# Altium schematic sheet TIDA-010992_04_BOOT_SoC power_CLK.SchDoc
size 431 x 279 mm; Date: Not shown in title block; ApprovedBy: Not shown in title block; CheckedBy: Not shown in title block; Author: Not shown in title block; CompanyName: Not shown in title block; Engineer: Not shown in title block; Organization: Not shown in title block; Address1: Not shown in title block; Address2: Not shown in title block; Address3: Not shown in title block; Address4: Not shown in title block; DocumentNumber: 4; Revision: Use project parameter SCH_Rev; SheetNumber: 4; SheetTotal: 13; PageSetup: Record=PageOptions¦CenterHorizontal=True¦CenterVertical=True¦PrintScale=1.00¦XCorrection=1.00¦YCorrection=1.00¦PrintKind=0¦BorderSize=5000000¦LeftOffset=0¦BottomOffset=0¦Orientation=2¦PaperLength=1000¦PaperWidth=1000¦Scale=100¦PaperSource=15¦PrintQuality=600¦MediaType=1¦DitherType=10¦PaperKind=Letter¦PrintScaleMode=1
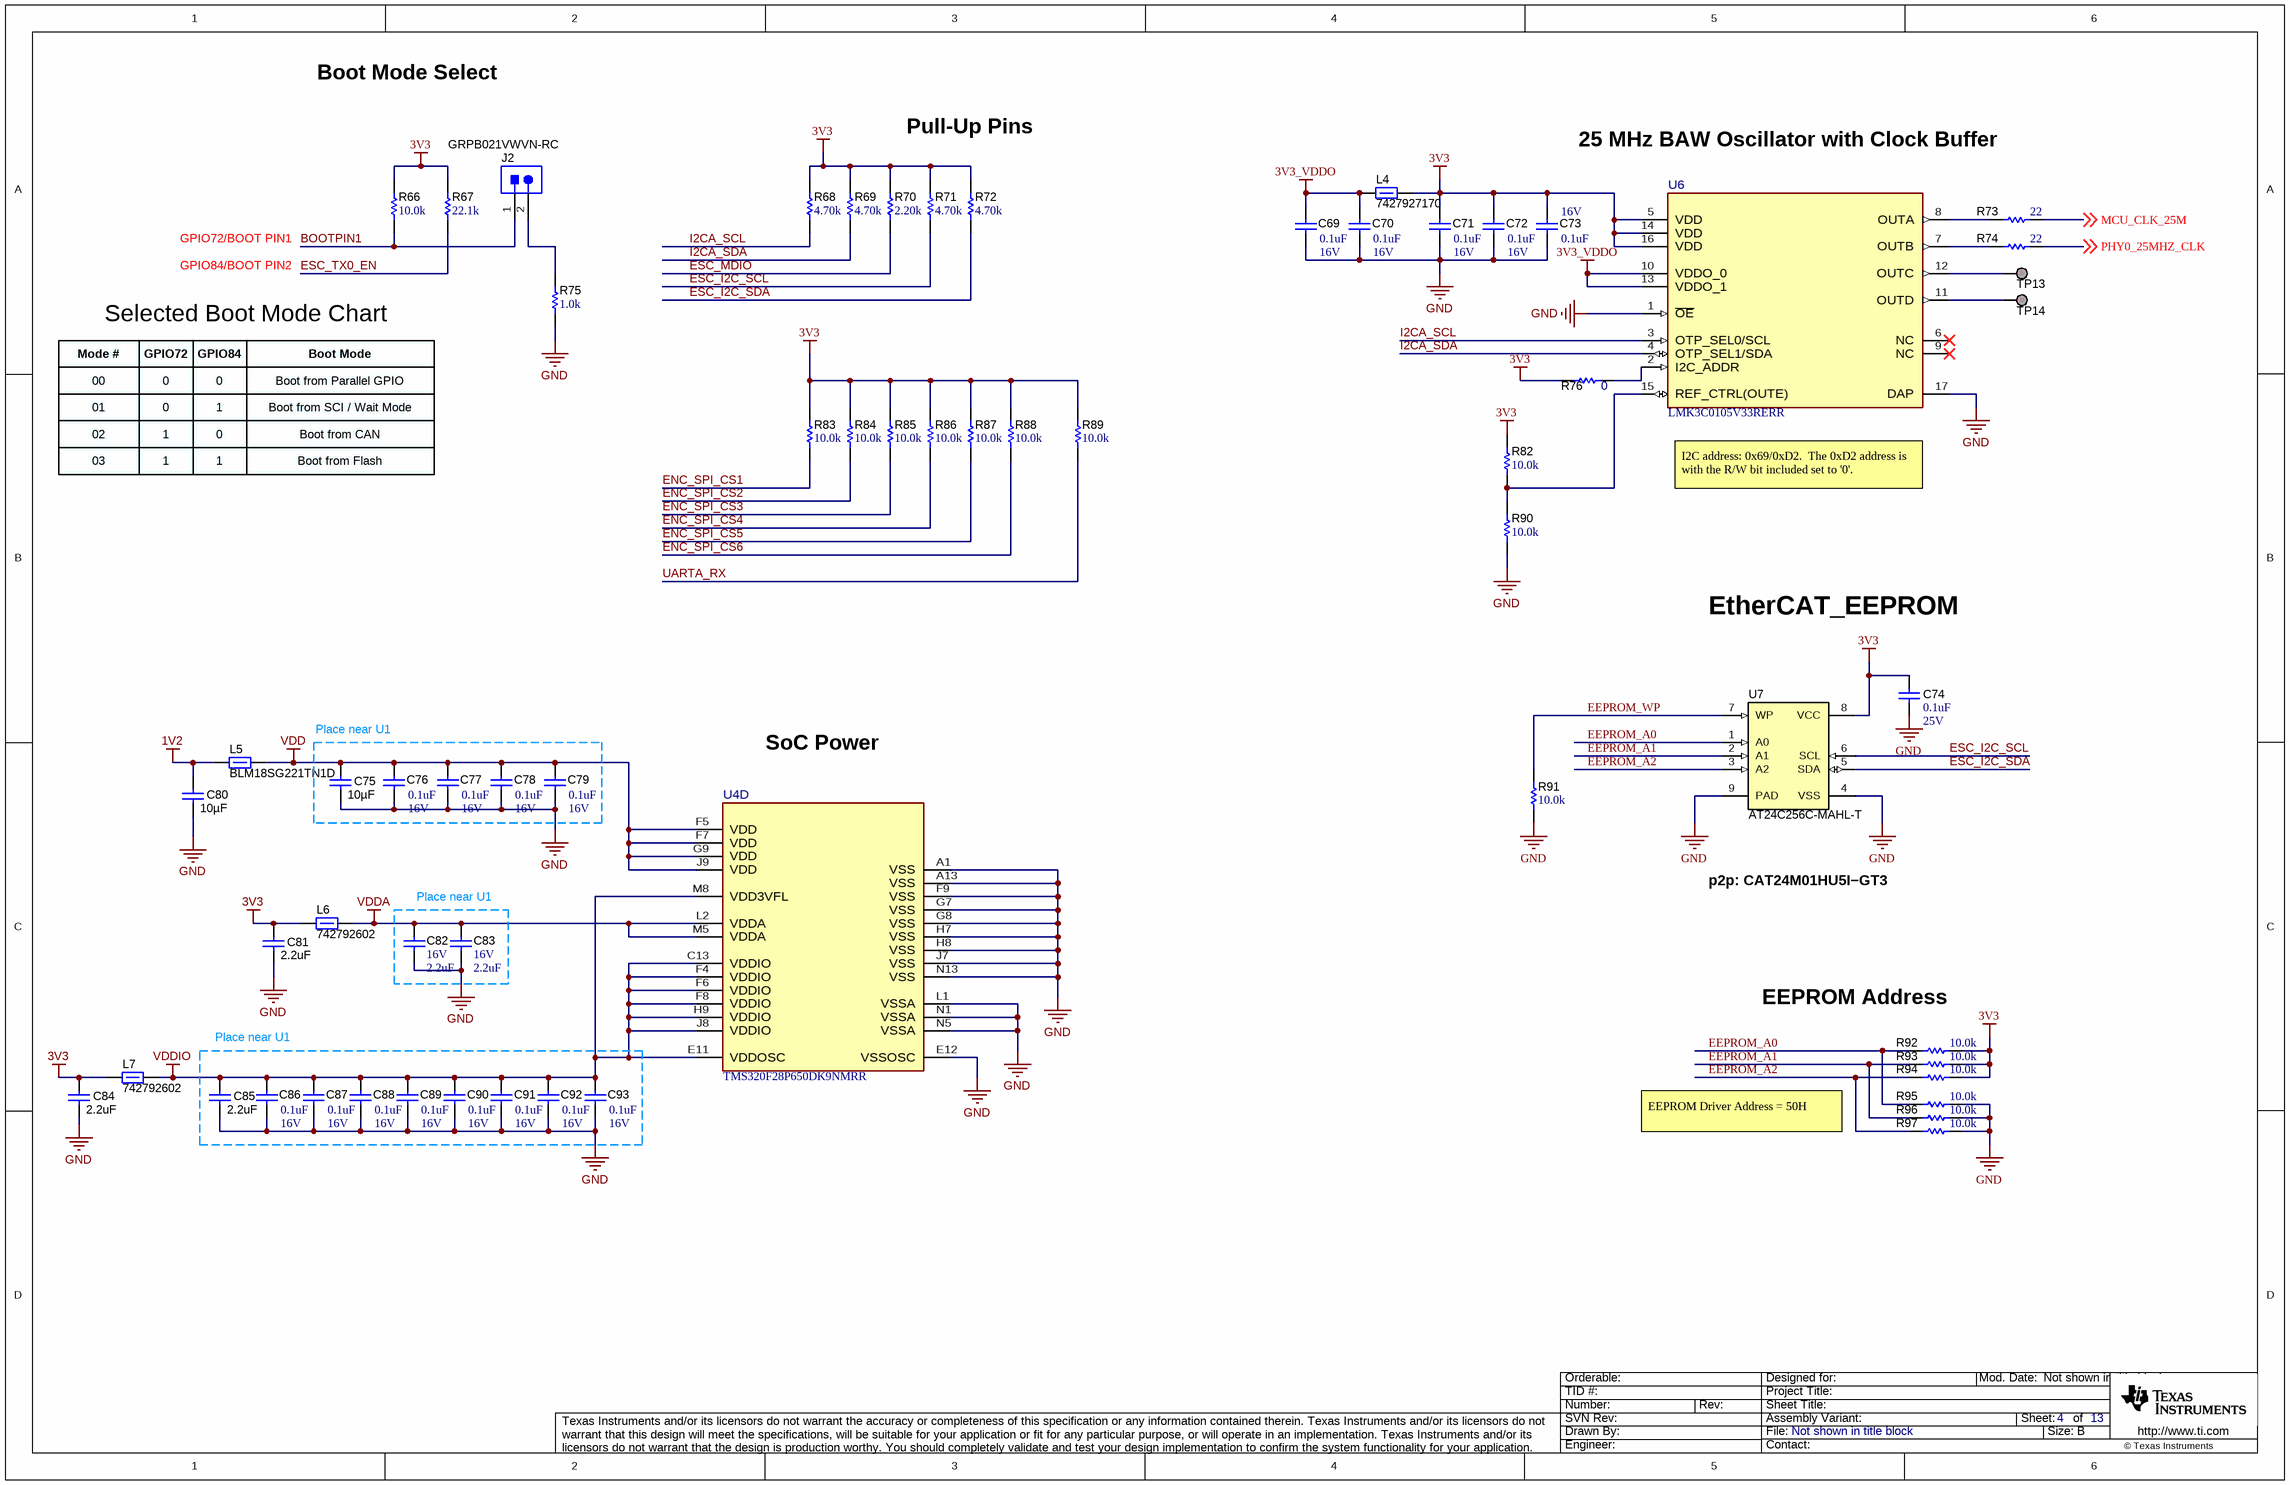
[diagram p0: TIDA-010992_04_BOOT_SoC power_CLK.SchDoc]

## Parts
C69  VDC_V: 16V  ValueDisplayed: 0.1uF  [0201]  (hidden comment: GRM033Z71C104KE14D)
C70  VDC_V: 16V  ValueDisplayed: 0.1uF  [0201]  (hidden comment: GRM033Z71C104KE14D)
C71  VDC_V: 16V  ValueDisplayed: 0.1uF  [0201]  (hidden comment: GRM033Z71C104KE14D)
C72  VDC_V: 16V  ValueDisplayed: 0.1uF  [0201]  (hidden comment: GRM033Z71C104KE14D)
C73  VDC_V: 16V  ValueDisplayed: 0.1uF  [0201]  (hidden comment: GRM033Z71C104KE14D)
C74  Value2: 25V  ValueDisplayed: 0.1uF  [0402]  (hidden comment: GRM155R71E104KE14D)
C75  ValueDisplayed: 10µF  [0603]  (hidden comment: GRM188R61C106KAALD)
C76  VDC_V: 16V  ValueDisplayed: 0.1uF  [0201]  (hidden comment: GRM033Z71C104KE14D)
C77  VDC_V: 16V  ValueDisplayed: 0.1uF  [0201]  (hidden comment: GRM033Z71C104KE14D)
C78  VDC_V: 16V  ValueDisplayed: 0.1uF  [0201]  (hidden comment: GRM033Z71C104KE14D)
C79  VDC_V: 16V  ValueDisplayed: 0.1uF  [0201]  (hidden comment: GRM033Z71C104KE14D)
C80  ValueDisplayed: 10µF  [0603]  (hidden comment: GRM188R61C106KAALD)
C81  ValueDisplayed: 2.2uF  [0603]  (hidden comment: 885012106018)
C82  VDC_V: 16V  ValueDisplayed: 2.2uF  [0402]  (hidden comment: GRM155R61C225KE11D)
C83  VDC_V: 16V  ValueDisplayed: 2.2uF  [0402]  (hidden comment: GRM155R61C225KE11D)
C84  ValueDisplayed: 2.2uF  [0603]  (hidden comment: 885012106018)
C85  ValueDisplayed: 2.2uF  [0603]  (hidden comment: 885012106018)
C86  VDC_V: 16V  ValueDisplayed: 0.1uF  [0201]  (hidden comment: GRM033Z71C104KE14D)
C87  VDC_V: 16V  ValueDisplayed: 0.1uF  [0201]  (hidden comment: GRM033Z71C104KE14D)
C88  VDC_V: 16V  ValueDisplayed: 0.1uF  [0201]  (hidden comment: GRM033Z71C104KE14D)
C89  VDC_V: 16V  ValueDisplayed: 0.1uF  [0201]  (hidden comment: GRM033Z71C104KE14D)
C90  VDC_V: 16V  ValueDisplayed: 0.1uF  [0201]  (hidden comment: GRM033Z71C104KE14D)
C91  VDC_V: 16V  ValueDisplayed: 0.1uF  [0201]  (hidden comment: GRM033Z71C104KE14D)
C92  VDC_V: 16V  ValueDisplayed: 0.1uF  [0201]  (hidden comment: GRM033Z71C104KE14D)
C93  VDC_V: 16V  ValueDisplayed: 0.1uF  [0201]  (hidden comment: GRM033Z71C104KE14D)
J2  GRPB021VWVN-RC  [Sullins_GRPB021VWVN-RC]
L4  7427927170  [0402]
L5  BLM18SG221TN1D  [0603]
L6  742792602  [0603]
L7  742792602  [0603]
R66  ValueDisplayed: 10.0k  [0402]  (hidden comment: ERJ-2RKF1002X)
R67  ValueDisplayed: 22.1k  [0402]  (hidden comment: CRCW040222K1FKED)
R68  ValueDisplayed: 4.70k  [0201]  (hidden comment: RC0201FR-7D4K7L)
R69  ValueDisplayed: 4.70k  [0201]  (hidden comment: RC0201FR-7D4K7L)
R70  ValueDisplayed: 2.20k  [0201]  (hidden comment: RC0201FR-072K2L)
R71  ValueDisplayed: 4.70k  [0201]  (hidden comment: RC0201FR-7D4K7L)
R72  ValueDisplayed: 4.70k  [0201]  (hidden comment: RC0201FR-7D4K7L)
R73  ValueDisplayed: 22  [0402L]  (hidden comment: CRCW040222R0JNED)
R74  ValueDisplayed: 22  [0402L]  (hidden comment: CRCW040222R0JNED)
R75  ValueDisplayed: 1.0k  [0402]  (hidden comment: ERJ-2GEJ102X)
R76  ValueDisplayed: 0  [0402]  (hidden comment: CRCW04020000Z0EDHP)
R82  ValueDisplayed: 10.0k  [0201]  (hidden comment: RC0201FS-7D10KL)
R83  ValueDisplayed: 10.0k  [0201]  (hidden comment: RC0201FS-7D10KL)
R84  ValueDisplayed: 10.0k  [0201]  (hidden comment: RC0201FS-7D10KL)
R85  ValueDisplayed: 10.0k  [0201]  (hidden comment: RC0201FS-7D10KL)
R86  ValueDisplayed: 10.0k  [0201]  (hidden comment: RC0201FS-7D10KL)
R87  ValueDisplayed: 10.0k  [0201]  (hidden comment: RC0201FS-7D10KL)
R88  ValueDisplayed: 10.0k  [0201]  (hidden comment: RC0201FS-7D10KL)
R89  ValueDisplayed: 10.0k  [0201]  (hidden comment: RC0201FS-7D10KL)
R90  ValueDisplayed: 10.0k  [0201]  (hidden comment: RC0201FS-7D10KL)
R91  ValueDisplayed: 10.0k  [0402]  (hidden comment: ERJ-2RKF1002X)
R92  ValueDisplayed: 10.0k  [0402]  (hidden comment: ERJ-2RKF1002X)
R93  ValueDisplayed: 10.0k  [0402]  (hidden comment: ERJ-2RKF1002X)
R94  ValueDisplayed: 10.0k  [0402]  (hidden comment: ERJ-2RKF1002X)
R95  ValueDisplayed: 10.0k  [0402]  (hidden comment: ERJ-2RKF1002X)
R96  ValueDisplayed: 10.0k  [0402]  (hidden comment: ERJ-2RKF1002X)
R97  ValueDisplayed: 10.0k  [0402]  (hidden comment: ERJ-2RKF1002X)
TP13  TP_SM_1MM  [TP_SM_1MM]  (value not drawn)  (no BOM)
TP14  TP_SM_1MM  [TP_SM_1MM]  (value not drawn)  (no BOM)
U4  TMS320F28P650DK9NMRR  [NMR0169A-MFG]  (part D of 4)
U6  LMK3C0105V33RERR  [RER0016A-MFG]
U7  AT24C256C-MAHL-T  [8MA2]

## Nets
1V2: C80.1 L5.1
3V3: C71.1 C72.1 C73.1 C74.2 C81.1 C84.1 L4.1 L6.1 L7.1 R66.1 R67.2 R68.2 R69.2 R70.2 R71.2 R72.2 R76.1 R82.2 R83.2 R84.2 R85.2 R86.2 R87.2 R88.2 R89.2 R92.1 R93.1 R94.1 U6.5(VDD) U6.14(VDD) U6.16(VDD) U7.8(VCC)
3V3_VDDO: C69.1 C70.1 L4.2 U6.10(VDDO_0) U6.13(VDDO_1)
GND: C69.2 C70.2 C71.2 C72.2 C73.2 C74.1 C75.2 C76.2 C77.2 C78.2 C79.2 C80.2 C81.2 C82.2 C83.2 C84.2 C85.2 C86.2 C87.2 C88.2 C89.2 C90.2 C91.2 C92.2 C93.2 R75.1 R90.1 R91.2 R95.1 R96.1 R97.1 U4.A1(VSS) U4.A13(VSS) U4.E12(VSSOSC) U4.F9(VSS) U4.G7(VSS) U4.G8(VSS) U4.H7(VSS) U4.H8(VSS) U4.J7(VSS) U4.L1(VSSA) U4.N1(VSSA) U4.N5(VSSA) U4.N13(VSS) U6.1(~{OE}) U6.17(DAP) U7.4(VSS) U7.9(PAD)
VDD: C75.1 C76.1 C77.1 C78.1 C79.1 L5.2 U4.F5(VDD) U4.F7(VDD) U4.G9(VDD) U4.J9(VDD)
VDDA: C82.1 C83.1 L6.2 U4.L2(VDDA) U4.M5(VDDA)
VDDIO: C85.1 C86.1 C87.1 C88.1 C89.1 C90.1 C91.1 C92.1 C93.1 L7.2 U4.C13(VDDIO) U4.E11(VDDOSC) U4.F4(VDDIO) U4.F6(VDDIO) U4.F8(VDDIO) U4.H9(VDDIO) U4.J8(VDDIO) U4.M8(VDD3VFL)
BOOTPIN1: J2.1 R66.2
EEPROM_A0: R92.2 R95.2 U7.1(A0)
EEPROM_A1: R93.2 R96.2 U7.2(A1)
EEPROM_A2: R94.2 R97.2 U7.3(A2)
EEPROM_WP: R91.1 U7.7(WP)
ENC_SPI_CS1: R83.1
ENC_SPI_CS2: R84.1
ENC_SPI_CS3: R85.1
ENC_SPI_CS4: R86.1
ENC_SPI_CS5: R87.1
ENC_SPI_CS6: R88.1
ESC_I2C_SCL: R71.1 U7.6(SCL)
ESC_I2C_SDA: R72.1 U7.5(SDA)
ESC_MDIO: R70.1
ESC_TX0_EN: R67.1
I2CA_SCL: R68.1 U6.3(OTP_SEL0/SCL)
I2CA_SDA: R69.1 U6.4(OTP_SEL1/SDA)
MCU_CLK_25M: R73.2 ; off-sheet MCU_CLK_25M
PHY0_25MHZ_CLK: R74.2 ; off-sheet PHY0_25MHZ_CLK
UARTA_RX: R89.1
NetJ2_2: J2.2 R75.2
NetR73_1: R73.1 U6.8(OUTA)
NetR74_1: R74.1 U6.7(OUTB)
NetR76_2: R76.2 U6.2(I2C_ADDR)
NetR82_1: R82.1 R90.2 U6.15(REF_CTRL(OUTE))
NetTP13_1: TP13.1 U6.12(OUTC)
NetTP14_1: TP14.1 U6.11(OUTD)

Not connected (* = marked no-connect by the designer): U6 6(NC)* 9(NC)*

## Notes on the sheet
- Boot Mode Select
- Pull-Up Pins
- 25 MHz BAW Oscillator with Clock Buffer
- GPIO72/BOOT PIN1
- GPIO84/BOOT PIN2
- Mode #
- GPIO72
- GPIO84
- Selected Boot Mode Chart
- Boot Mode
- 00
- 01
- 02
- 0
- 1
- Boot from Parallel GPIO
- Boot from SCI / Wait Mode
- Boot from CAN
- 03
- Boot from Flash
- (near U6) I2C address: 0x69/0xD2.  The 0xD2 address is with the R/W bit included set to '0'.
- EtherCAT_EEPROM
- Place near U1
- SoC Power
- p2p: CAT24M01HU5I−GT3
- EEPROM Address
- EEPROM Driver Address = 50H

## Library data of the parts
C69-C73 C76-C79 C86-C93 = CMP-0064970-1: CAP, CERM, 0.1 uF, 16 V,+/- 10%, X7R, 0201; Manufacturer: MuRata; TaMin_C: -55°C; Polarized: N; SizeAreaWB_mm2: 2.08; Value1: Unknown; U/M: EA; Value: 0.1uF; TaMax_C: 125°C; SizeZ_mm: 0.26; SizeX_mm: 0.6; SizeY_mm: 0.3; SizeArea_mm2: 0.18; Cap_F: 100nF; AEC Category: Q200
C74 = CMP-0006659-2: CAP, CERM, 0.1 uF, 25 V, +/- 10%, X7R, 0402; Manufacturer: MuRata; TaMin_C: -55°C; Polarized: N; SizeAreaWB_mm2: 3; U/M: EA; Value: 0.1uF; TaMax_C: 125°C; SizeZ_mm: 0.6; SizeX_mm: 1; SizeY_mm: 0.5; Cap_F: 100nF; AEC Category: Q200; Value1: Unknown
C75 C80 = CMP-0086225-1: CAP, CERM, 10 µF, 16 V,+/- 10%, X5R, 0603; Manufacturer: MuRata; SizeZ_mm: 1; SizeX_mm: 1.6; SizeArea_mm2: 1.28; VDC_V: 16V; U/M: EA; AEC Category: Q200; SizeY_mm: 0.8; Polarized: N; TaMax_C: 85°C; Value: 10uF; SizeAreaWB_mm2: 4.68; TaMin_C: -55°C
C81 C84 C85 = CMP-0006825-5: CAP, CERM, 2.2 uF, 16 V, +/- 20%, X5R, 0603; Manufacturer: Wurth Elektronik; TaMin_C: -55°C; Polarized: N; SizeAreaWB_mm2: 4.68; Value1: Unknown; U/M: EA; Value: 2.2uF; TaMax_C: 85°C; SizeZ_mm: 1; SizeX_mm: 1.6; SizeY_mm: 0.8; Value2: 16V; SizeArea_mm2: 1.28; Cap_F: 2.2µF; AEC Category: Q200
C82 C83 = CMP-0006594-2: CAP, CERM, 2.2 uF, 16 V, +/- 10%, X5R, 0402; Manufacturer: MuRata; TaMin_C: -55°C; Polarized: N; SizeAreaWB_mm2: 3; Value1: Unknown; U/M: EA; Value: 2.2uF; TaMax_C: 85°C; SizeZ_mm: 0.6; SizeX_mm: 1; SizeY_mm: 0.5; Cap_F: 2.2µF; AEC Category: Q200
J2 = CMP-0054555-1: Header, 50mil, 2x1, Gold, TH; Manufacturer: Sullins Connector Solutions; CNHeader: TRUE; Green_Lifecycle: Not Set; Green_REACh: Incomplete; CT: FALSE
L4 = CMP-0003226-1: Ferrite Bead, 75 ohm @ 100 MHz, 0.3 A, 0402; Manufacturer: Wurth Elektronik; Ztyp@1GHz_Ohm: 541.253; ZTyp@100MHz_Ohm: 75; SizeAreaWB_mm2: 3; DCR_ohm: 0.31; Value1: 0.31 ohm; Value: 75 ohm; Imax_A: 300mA; SizeZ_mm: 0.6; SizeX_mm: 1; SizeY_mm: 0.5; Value2: 0.3A
L5 = CMP-0003353-2: Ferrite Bead, 220 ohm @ 100 MHz, 2.5 A, 0603; Manufacturer: MuRata; ZTyp@100MHz_Ohm: 220; SizeAreaWB_mm2: 4.68; DCR_ohm: 40m; Value1: 0.04 ohm; Value: 220 ohm; Imax_A: 2.5A; SizeZ_mm: 1; SizeX_mm: 1.6; SizeY_mm: 0.8; SizeArea_mm2: 1.28
L6 L7 = CMP-0003173-2: Ferrite Bead, 60 ohm @ 100 MHz, 3 A, 0603; Manufacturer: Wurth Elektronik; Ztyp@1GHz_Ohm: 110.436; ZTyp@100MHz_Ohm: 60; SizeAreaWB_mm2: 4.68; DCR_ohm: 40m; Value1: 0.04 ohm; Value: 60 ohm; Imax_A: 3A; SizeZ_mm: 1; SizeX_mm: 1.6; SizeY_mm: 0.8; SizeArea_mm2: 1.28
R66 R91-R97 = CMP-0026658-1: RES, 10.0 k, 1%, 0.1 W, 0402; Manufacturer: Panasonic; Power_W: 100mW; TempCo: 100 ppm/C; Value_Code: 10k0; U/M: EA; Value: 10.0k; EIA_Code: E96; Res_ohm: 10k; SizeX_mm: 1; SizeY_mm: 0.5; SizeZ_mm: 0.6; Value2: 0.1W; VDC_V: 50V; AEC Category: Q200
R67 = CMP-0026178-2: RES, 22.1 k, 1%, 0.063 W, AEC-Q200 Grade 0, 0402; Manufacturer: Vishay-Dale; Power_W: 63mW; TempCo: 100 ppm/C; Value_Code: 22k1; Value: 22.1k; EIA_Code: E96; SizeX_mm: 1; SizeY_mm: 0.5; SizeZ_mm: 0.6; Value2: 0.063W; AEC Qualified: Y; VDC_V: 50V; AEC Category: Q200; AEC Grade: 0
R68 R69 R71 R72 = CMP-0028031-1: RES, 4.70 k, 1%, 0.05 W, 0201; Manufacturer: Yageo America; Power_W: 50mW; TempCo: 200 ppm/C; Value_Code: 4k70; U/M: EA; Value: 4.70k; Res_ohm: 4.7k; SizeX_mm: 0.6; SizeY_mm: 0.3; SizeZ_mm: 0.26; Value2: 0.05W; SizeArea_mm2: 0.18; AEC Qualified: N; VDC_V: 25V; AEC Category: Q200
R70 = CMP-0027558-1: RES, 2.20 k, 1%, 0.05 W, 0201; Manufacturer: Yageo America; Power_W: 50mW; TempCo: 200 ppm/C; Value_Code: 2k20; U/M: EA; Value: 2.20k; Res_ohm: 2.2k; SizeX_mm: 0.6; SizeY_mm: 0.3; SizeZ_mm: 0.26; Value2: 0.05W; SizeArea_mm2: 0.18; AEC Qualified: N; VDC_V: 25V; AEC Category: Q200
R73 R74 = CMP-0026880-3: RES, 22, 5%, 0.063 W, AEC-Q200 Grade 0, 0402; Manufacturer: Vishay-Dale; Power_W: 63mW; TempCo: 200 ppm/C; Value_Code: 22R0; Value: 22; EIA_Code: E24; SizeX_mm: 1; SizeY_mm: 0.5; SizeZ_mm: 0.6; Value2: 0.063W; AEC Qualified: Y; VDC_V: 50V; AEC Category: Q200; AEC Grade: 0
R75 = CMP-0078193-1: RES, 1.0 k, 5%, 0.1 W, AEC-Q200 Grade 0, 0402; Manufacturer: Panasonic; Value_Code: 1k00; SizeArea_mm2: 0.5; AEC Qualified: Y; AEC Category: Q200; Res_ohm: 1k; Value: 1.0k; SizeZ_mm: 0.6; Green_REACh: Passed; EIA_Code: E24; TempCo: 200 ppm/C; AEC Grade: 0; Power_W: 100mW; VDC_V: 50V; Value2: 0.1W; Green_Lifecycle: Active; U/M: EA; SizeX_mm: 1
R76 = CMP-0081856-1: RES, 0, 0%, 0.2 W, AEC-Q200 Grade 0, 0402; Manufacturer: Vishay-Dale; SizeAreaWB_mm2: 3; SizeArea_mm2: 0.5; AEC Qualified: Y; AEC Category: Q200; Value: 0; SizeZ_mm: 0.6; Power_W: 200mW; VDC_V: 50V; Value2: 0.2W; SizeX_mm: 1
R82-R90 = CMP-0028071-1: RES, 10.0 k, 1%, 0.05 W, 0201; Manufacturer: Yageo America; Power_W: 50mW; TempCo: 200 ppm/C; Value_Code: 10k0; U/M: EA; Value: 10.0k; EIA_Code: E96; Res_ohm: 10k; SizeX_mm: 0.6; SizeY_mm: 0.3; SizeZ_mm: 0.26; Value2: 0.05W; SizeArea_mm2: 0.18; AEC Qualified: N; VDC_V: 25V; AEC Category: Q200
TP13 TP14 = CMP-0003825-1: 1mm Test Point, SMT; Manufacturer: Any
U4 = CMP-0098413-1: Real-Time Microcontroller, NFBGA169; Manufacturer: Texas Instruments; SizeZ_mm: 1mm; AEC Qualified: No; Core Architecture: C28x; Data Bus Width: 32bits; Frequency_Fixed: 200MHz; Interface: I2C,SPI,UART,CAN,USB,LIN,SCI,Ethernet; Max Supply Voltage: 3.63V; Memory Size: 1.28MBytes; Memory Type: FLASH; Min Supply Voltage: 1.14V; Number Of A/D Converters: 3; Number Of Adc Channels: 34; Number Of Cores: 2; Number Of Ethernet Channels: 1; Number Of I/Os: 119; Number Of Pwm Channels: 36; Number Of Spi Channels: 4; Number Of Timers/Counters: 6; Ram Size: 248KBytes; Standoff Height: 0.19mm; TaMax_C: +125°C; TaMin_C: -40°C; TJmax_C: +155°C
U6 = CMP-0126121-1: 5 output reference-less clock generator with bulk acoustic wave (BAW) 16-TQFN -40 to 85; Manufacturer: Texas Instruments; SizeZ_mm: 1.2mm; AEC Qualified: No; Interface: I2C; Max Frequency: 200MHz; Max Supply Voltage: 3.465V; Min Supply Voltage: 1.71V; Number Of Outputs: 5; Standoff Height: 0mm; TaMax_C: +85°C; TaMin_C: -40°C; TJmax_C: +105°C
U7 = CMP-0005119-3: I2C-Compatible (2-Wire) Serial EEPROM 256 kb, 8UDFN; Manufacturer: Atmel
